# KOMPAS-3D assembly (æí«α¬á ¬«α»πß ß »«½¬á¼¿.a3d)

Referenced files in D:\МОДЕЛЬ ТАНКА Т90\ПОДСБОРКИ\КОРПУС\: Сборка дно с пластиком.a3d, Сборка борт левый с пластиком.a3d, Сборка борт правый с пластиком.a3d, Сборка корпус лоб.a3d, Сборка корпус верх.a3d, Сборка корма.a3d, Сборка корма верх.a3d, Сборка крышка моторного.a3d, Сборка полка надгусеничная левая.a3d, Сборка полка надгусеничная правая.a3d
Referenced files in D:\МОДЕЛЬ ТАНКА Т90\ДЕТАЛИ\КОРПУС\МЕТАЛЛ\: перемычка корпуса.m3d, дно1скос.m3d, дно2 скос .m3d, тяга отвала.m3d, отвал.m3d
